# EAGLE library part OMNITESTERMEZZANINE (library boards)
Mezzanine card between the omnitester and the bed of nails.
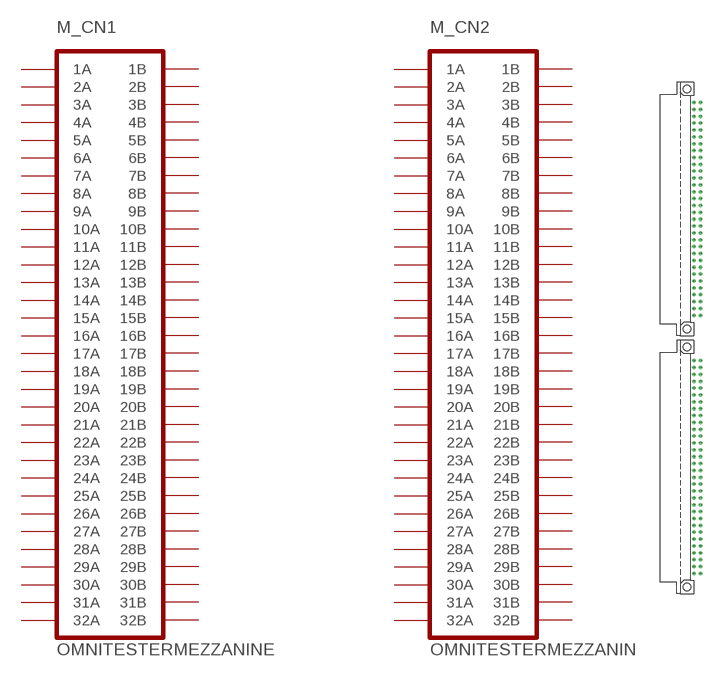
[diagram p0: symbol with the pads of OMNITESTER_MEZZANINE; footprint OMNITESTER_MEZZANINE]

Designator prefix M; gates _CN1=DIN41612_B64_MALE _CN2=DIN41612_B64_MALE

## OMNITESTERMEZZANINE  [OMNITESTER_MEZZANINE]
1A1  _CN2:1A
1A2  _CN1:1A
1B1  _CN2:1B
1B2  _CN1:1B
2A1  _CN2:2A
2A2  _CN1:2A
2B1  _CN2:2B
2B2  _CN1:2B
3A1  _CN2:3A
3A2  _CN1:3A
3B1  _CN2:3B
3B2  _CN1:3B
4A1  _CN2:4A
4A2  _CN1:4A
4B1  _CN2:4B
4B2  _CN1:4B
5A1  _CN2:5A
5A2  _CN1:5A
5B1  _CN2:5B
5B2  _CN1:5B
6A1  _CN2:6A
6A2  _CN1:6A
6B1  _CN2:6B
6B2  _CN1:6B
7A1  _CN2:7A
7A2  _CN1:7A
7B1  _CN2:7B
7B2  _CN1:7B
8A1  _CN2:8A
8A2  _CN1:8A
8B1  _CN2:8B
8B2  _CN1:8B
9A1  _CN2:9A
9A2  _CN1:9A
9B1  _CN2:9B
9B2  _CN1:9B
10A1  _CN2:10A
10A2  _CN1:10A
10B1  _CN2:10B
10B2  _CN1:10B
11A1  _CN2:11A
11A2  _CN1:11A
11B1  _CN2:11B
11B2  _CN1:11B
12A1  _CN2:12A
12A2  _CN1:12A
12B1  _CN2:12B
12B2  _CN1:12B
13A1  _CN2:13A
13A2  _CN1:13A
13B1  _CN2:13B
13B2  _CN1:13B
14A1  _CN2:14A
14A2  _CN1:14A
14B1  _CN2:14B
14B2  _CN1:14B
15A1  _CN2:15A
15A2  _CN1:15A
15B1  _CN2:15B
15B2  _CN1:15B
16A1  _CN2:16A
16A2  _CN1:16A
16B1  _CN2:16B
16B2  _CN1:16B
17A1  _CN2:17A
17A2  _CN1:17A
17B1  _CN2:17B
17B2  _CN1:17B
18A1  _CN2:18A
18A2  _CN1:18A
18B1  _CN2:18B
18B2  _CN1:18B
19A1  _CN2:19A
19A2  _CN1:19A
19B1  _CN2:19B
19B2  _CN1:19B
20A1  _CN2:20A
20A2  _CN1:20A
20B1  _CN2:20B
20B2  _CN1:20B
21A1  _CN2:21A
21A2  _CN1:21A
21B1  _CN2:21B
21B2  _CN1:21B
22A1  _CN2:22A
22A2  _CN1:22A
22B1  _CN2:22B
22B2  _CN1:22B
23A1  _CN2:23A
23A2  _CN1:23A
23B1  _CN2:23B
23B2  _CN1:23B
24A1  _CN2:24A
24A2  _CN1:24A
24B1  _CN2:24B
24B2  _CN1:24B
25A1  _CN2:25A
25A2  _CN1:25A
25B1  _CN2:25B
25B2  _CN1:25B
26A1  _CN2:26A
26A2  _CN1:26A
26B1  _CN2:26B
26B2  _CN1:26B
27A1  _CN2:27A
27A2  _CN1:27A
27B1  _CN2:27B
27B2  _CN1:27B
28A1  _CN2:28A
28A2  _CN1:28A
28B1  _CN2:28B
28B2  _CN1:28B
29A1  _CN2:29A
29A2  _CN1:29A
29B1  _CN2:29B
29B2  _CN1:29B
30A1  _CN2:30A
30A2  _CN1:30A
30B1  _CN2:30B
30B2  _CN1:30B
31A1  _CN2:31A
31A2  _CN1:31A
31B1  _CN2:31B
31B2  _CN1:31B
32A1  _CN2:32A
32A2  _CN1:32A
32B1  _CN2:32B
32B2  _CN1:32B

## Footprint OMNITESTER_MEZZANINE (pad centres in mm)
drill 0.8 octagon: 1A1 0.254,8.89; 1A2 0.254,-86.677; 1B1 2.794,8.89; 1B2 2.794,-86.677; 2A1 0.254,11.43; 2A2 0.254,-84.138; 2B1 2.794,11.43; 2B2 2.794,-84.138; 3A1 0.254,13.97; 3A2 0.254,-81.597; 3B1 2.794,13.97; 3B2 2.794,-81.597; 4A1 0.254,16.51; 4A2 0.254,-79.058; 4B1 2.794,16.51; 4B2 2.794,-79.058; 5A1 0.254,19.05; 5A2 0.254,-76.517; 5B1 2.794,19.05; 5B2 2.794,-76.517; 6A1 0.254,21.59; 6A2 0.254,-73.978; 6B1 2.794,21.59; 6B2 2.794,-73.978; 7A1 0.254,24.13; 7A2 0.254,-71.438; 7B1 2.794,24.13; 7B2 2.794,-71.438; 8A1 0.254,26.67; 8A2 0.254,-68.897; 8B1 2.794,26.67; 8B2 2.794,-68.897; 9A1 0.254,29.21; 9A2 0.254,-66.358; 9B1 2.794,29.21; 9B2 2.794,-66.358; 10A1 0.254,31.75; 10A2 0.254,-63.818; 10B1 2.794,31.75; 10B2 2.794,-63.818; 11A1 0.254,34.29; 11A2 0.254,-61.278; 11B1 2.794,34.29; 11B2 2.794,-61.278; 12A1 0.254,36.83; 12A2 0.254,-58.737; 12B1 2.794,36.83; 12B2 2.794,-58.737; 13A1 0.254,39.37; 13A2 0.254,-56.197; 13B1 2.794,39.37; 13B2 2.794,-56.197; 14A1 0.254,41.91; 14A2 0.254,-53.657; 14B1 2.794,41.91; 14B2 2.794,-53.657; 15A1 0.254,44.45; 15A2 0.254,-51.117; 15B1 2.794,44.45; 15B2 2.794,-51.117; 16A1 0.254,46.99; 16A2 0.254,-48.578; 16B1 2.794,46.99; 16B2 2.794,-48.578; 17A1 0.254,49.53; 17A2 0.254,-46.038; 17B1 2.794,49.53; 17B2 2.794,-46.038; 18A1 0.254,52.07; 18A2 0.254,-43.498; 18B1 2.794,52.07; 18B2 2.794,-43.498; 19A1 0.254,54.61; 19A2 0.254,-40.958; 19B1 2.794,54.61; 19B2 2.794,-40.958; 20A1 0.254,57.15; 20A2 0.254,-38.417; 20B1 2.794,57.15; 20B2 2.794,-38.417; 21A1 0.254,59.69; 21A2 0.254,-35.877; 21B1 2.794,59.69; 21B2 2.794,-35.877; 22A1 0.254,62.23; 22A2 0.254,-33.337; 22B1 2.794,62.23; 22B2 2.794,-33.337; 23A1 0.254,64.77; 23A2 0.254,-30.797; 23B1 2.794,64.77; 23B2 2.794,-30.797; 24A1 0.254,67.31; 24A2 0.254,-28.258; 24B1 2.794,67.31; 24B2 2.794,-28.258; 25A1 0.254,69.85; 25A2 0.254,-25.718; 25B1 2.794,69.85; 25B2 2.794,-25.718; 26A1 0.254,72.39; 26A2 0.254,-23.177; 26B1 2.794,72.39; 26B2 2.794,-23.177; 27A1 0.254,74.93; 27A2 0.254,-20.637; 27B1 2.794,74.93; 27B2 2.794,-20.637; 28A1 0.254,77.47; 28A2 0.254,-18.098; 28B1 2.794,77.47; 28B2 2.794,-18.098; 29A1 0.254,80.01; 29A2 0.254,-15.557; 29B1 2.794,80.01; 29B2 2.794,-15.557; 30A1 0.254,82.55; 30A2 0.254,-13.018; 30B1 2.794,82.55; 30B2 2.794,-13.018; 31A1 0.254,85.09; 31A2 0.254,-10.477; 31B1 2.794,85.09; 31B2 2.794,-10.477; 32A1 0.254,87.63; 32A2 0.254,-7.938; 32B1 2.794,87.63; 32B2 2.794,-7.938
hole 2.8 at -2.286,92.71
hole 2.8 at -2.286,3.81
hole 2.8 at -2.286,-2.857
hole 2.8 at -2.286,-91.757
